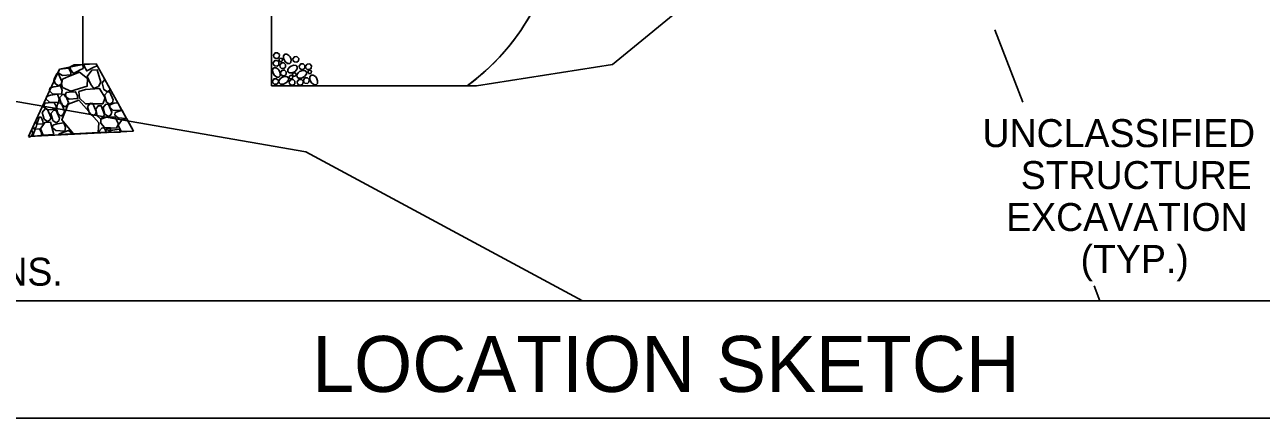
# Model space of a CAD drawing. Extents: x 471 to 2034, y -623 to 126.
# Drawn here: x 632.5 to 720.8, y -339.9 to -311.7 of the extents above; entities that cross this region are included whole.
import ezdxf

# ---------------------------------------------------------------- set-up
doc = ezdxf.new("R2010")
doc.units = 0
for name, color, linetype in [('Default', 7, 'Continuous'), ('Exist Hydro Stream or Body of Water', 7, 'Continuous'), ('Exist Vegetation Woods Line', 7, 'Continuous'), ('Miscellaneous Lines CELL', 7, 'Continuous'), ('Plan Sheet CELL', 7, 'Continuous'), ('Sup Concrete Girder Lines', 7, 'Continuous'), ('Text', 7, 'Continuous'), ('Title Text', 7, 'Continuous')]:
    doc.layers.add(name, color=color, linetype=linetype)

msp = doc.modelspace()

# ---------------------------------------------------------------- linework, layer by layer
at = {"layer": 'Default'}
for p, q in [((636.644, -299.662), (636.642, -314.576)), ((681.665, -308.67), (674.472, -314.579)), ((674.472, -314.579), (681.665, -308.67)), ((636.026, -314.603), (636.642, -314.575)), ((636.642, -314.575), (636.642, -314.575)), ((636.741, -314.572), (637.59, -314.535)), ((637.656, -314.654), (637.59, -314.535)), ((674.472, -314.579), (664.751, -316.1)), ((664.751, -316.1), (674.472, -314.579)), ((634.778, -315.233), (634.58, -315.676)), ((635.187, -315.643), (635.118, -315.981)), ((638.21, -315.651), (638.594, -316.343)), ((634.254, -316.406), (634.319, -316.262)), ((664.751, -316.1), (664.087, -316.1)), ((664.087, -316.1), (664.751, -316.1)), ((634.824, -317.421), (634.758, -317.744)), ((639.436, -317.867), (639.137, -317.319)), ((633.037, -319.141), (633.257, -318.64)), ((633.354, -318.85), (633.534, -318.346)), ((639.774, -318.47), (640.267, -319.35)), ((632.766, -319.739), (632.978, -319.263)), ((633.231, -319.208), (633.06, -319.695)), ((634.573, -319.596), (633.811, -319.63)), ((635.899, -319.539), (634.897, -319.582)), ((637.745, -319.456), (635.965, -319.533)), ((638.317, -319.431), (637.834, -319.452)), ((638.64, -319.266), (638.292, -319.281)), ((638.46, -319.449), (639.324, -319.412)), ((639.37, -319.385), (640.267, -319.346))]:
    msp.add_line(p, q, dxfattribs=at)
for points in [[(634.965, -314.907), (635.189, -314.885), (635.638, -314.852), (635.776, -315.147), (635.784, -315.334), (635.186, -315.373), (634.877, -315.173), (634.965, -314.907)], [(635.187, -315.643), (635.454, -315.503), (636.414, -315.135), (636.972, -315.587), (636.958, -316.125), (635.785, -316.489), (635.198, -316.227), (635.118, -315.981)], [(636.653, -314.875), (636.444, -314.959), (635.968, -315.217), (635.755, -314.939), (635.747, -314.752), (636.026, -314.603)], [(636.64, -314.576), (636.653, -314.875)], [(637.658, -314.681), (637.437, -314.778), (636.923, -315.038), (636.76, -314.745), (636.741, -314.572)], [(637.416, -316.305), (637.216, -316.014), (636.953, -315.437), (637.272, -314.998), (637.671, -314.968), (637.922, -315.858), (637.748, -316.166), (637.416, -316.305)], [(637.656, -314.654), (637.658, -314.681)], [(634.902, -316.118), (634.657, -315.953), (634.58, -315.676)], [(634.778, -315.233), (634.914, -315.254), (635.139, -315.807), (635.084, -315.997), (634.902, -316.118)], [(638.39, -316.54), (638.145, -316.375), (638.011, -315.893), (638.21, -315.651)], [(634.044, -316.882), (634.339, -316.781), (634.824, -316.71), (634.951, -317.042), (634.9, -317.307), (634.261, -317.273), (634.027, -317.07), (634.044, -316.882)], [(634.319, -316.262), (634.561, -316.179), (635.046, -316.108), (635.173, -316.44), (635.122, -316.705), (634.483, -316.671), (634.249, -316.468), (634.254, -316.406)], [(635.346, -317.609), (635.114, -317.444), (634.968, -316.963), (635.183, -316.728), (635.37, -316.72), (635.62, -317.297), (635.53, -317.526), (635.346, -317.609)], [(635.452, -316.591), (635.676, -316.569), (636.125, -316.537), (636.263, -316.831), (636.271, -317.018), (635.672, -317.057), (635.363, -316.858), (635.452, -316.591)], [(636.35, -316.527), (636.832, -316.381), (637.842, -316.312), (638.234, -316.97), (638.064, -317.391), (636.826, -317.395), (636.396, -317), (636.35, -316.527)], [(638.567, -317.433), (638.322, -317.269), (638.188, -316.786), (638.39, -316.54), (638.579, -316.569), (638.803, -317.123), (638.749, -317.313), (638.567, -317.433)], [(638.594, -316.343), (638.572, -316.419), (638.39, -316.54)], [(634.115, -318.655), (633.87, -318.491), (633.737, -318.009), (633.939, -317.762), (634.128, -317.791), (634.352, -318.345), (634.298, -318.535), (634.115, -318.655)], [(633.931, -317.35), (634.155, -317.328), (634.604, -317.296), (634.742, -317.59), (634.75, -317.777), (634.151, -317.816), (633.842, -317.617), (633.931, -317.35)], [(634.736, -318.744), (634.491, -318.579), (634.358, -318.097), (634.559, -317.851), (634.748, -317.88), (634.973, -318.433), (634.918, -318.623), (634.736, -318.744)], [(635.062, -318.272), (634.853, -318.056), (634.758, -317.744)], [(634.824, -317.421), (634.884, -317.342), (635.109, -317.332), (635.336, -317.948), (635.245, -318.152), (635.062, -318.272)], [(635.965, -319.534), (635.136, -318.532), (635.588, -317.411), (636.364, -317.127), (637.786, -318.754), (637.745, -319.456)], [(637.351, -318.248), (637.118, -318.083), (636.985, -317.6), (637.174, -317.354), (637.363, -317.384), (637.6, -317.936), (637.533, -318.127), (637.351, -318.248)], [(637.899, -318.474), (637.664, -318.259), (637.569, -317.788), (637.733, -317.543), (637.958, -317.533), (638.185, -318.161), (638.081, -318.353), (637.899, -318.474)], [(638.467, -318.311), (638.222, -318.147), (638.089, -317.665), (638.291, -317.418), (638.48, -317.448), (638.704, -318.001), (638.65, -318.191), (638.467, -318.311)], [(639.436, -317.867), (639.432, -317.884), (638.793, -317.849), (638.559, -317.647), (638.575, -317.458)], [(638.575, -317.458), (638.871, -317.358), (639.137, -317.319)], [(633.257, -318.637), (633.358, -318.885), (633.303, -319.075), (633.121, -319.195)], [(633.532, -318.349), (633.657, -318.34), (633.795, -318.634), (633.803, -318.822), (633.356, -318.851)], [(633.814, -319.627), (633.607, -319.173), (633.926, -318.734), (634.325, -318.704), (634.577, -319.594)], [(637.925, -318.498), (638.319, -318.355), (638.918, -318.317), (639.177, -318.819), (639.041, -319.137), (638.176, -319.1), (637.937, -318.785), (637.925, -318.498)], [(639.759, -318.436), (639.162, -318.403), (638.928, -318.201), (638.945, -318.012)], [(638.945, -318.012), (639.241, -317.912), (639.443, -317.882)], [(639.37, -319.385), (639.164, -318.931), (639.482, -318.492), (639.776, -318.47)], [(639.442, -317.882), (639.443, -317.882), (639.757, -318.435)], [(632.978, -319.262), (633.06, -319.466), (633.006, -319.656), (632.823, -319.776)], [(633.121, -319.195), (633.034, -319.137)], [(633.231, -319.208), (633.541, -319.186), (633.679, -319.48), (633.687, -319.668), (633.088, -319.706), (633.06, -319.696)], [(634.503, -318.922), (634.798, -318.822), (635.283, -318.751), (635.41, -319.083), (635.359, -319.348), (634.72, -319.313), (634.486, -319.111), (634.503, -318.922)], [(634.897, -319.58), (634.942, -319.541), (635.608, -319.299), (635.899, -319.536)], [(637.834, -319.452), (637.808, -319.357), (638.01, -319.111), (638.199, -319.14), (638.317, -319.431)], [(638.292, -319.281), (638.408, -319.139), (638.597, -319.168), (638.64, -319.266)], [(638.46, -319.449), (638.466, -319.382)], [(638.466, -319.382), (638.762, -319.282), (639.247, -319.21), (639.324, -319.412)], [(632.823, -319.776), (632.765, -319.737)]]:
    msp.add_lwpolyline(points, dxfattribs=at)
msp.add_arc((654.611, -303.102), 16.085, 306.09259, 354.38534, dxfattribs=at)
at = {"layer": 'Exist Hydro Stream or Body of Water'}
for points in [[(703.76, -317.276), (701.758, -312.107)], [(709.258, -331.475), (708.844, -330.406)]]:
    msp.add_lwpolyline(points, dxfattribs=at)
at = {"layer": 'Exist Vegetation Woods Line'}
msp.add_lwpolyline([(564.339, -320.555), (625.254, -316.095), (652.558, -320.834), (672.318, -331.475)], dxfattribs=at)
at = {"layer": 'Miscellaneous Lines CELL'}
for points in [[(650.229, -314.469), (650.341, -314.31), (650.52, -314.3), (650.645, -314.429), (650.627, -314.609), (650.516, -314.701), (650.34, -314.688), (650.256, -314.608), (650.229, -314.469)], [(650.261, -313.916), (650.373, -313.756), (650.552, -313.746), (650.676, -313.875), (650.658, -314.056), (650.548, -314.148), (650.371, -314.135), (650.288, -314.054), (650.261, -313.916)], [(650.646, -314.242), (650.713, -314.147), (650.82, -314.141), (650.895, -314.218), (650.884, -314.326), (650.818, -314.382), (650.712, -314.374), (650.662, -314.326), (650.646, -314.242)], [(651.437, -314.028), (651.52, -314.238), (651.503, -314.431), (651.416, -314.522), (651.26, -314.519), (651.083, -314.38), (650.975, -314.166), (650.972, -313.963), (651.053, -313.849), (651.214, -313.839), (651.358, -313.931), (651.442, -314.037)], [(651.638, -314.187), (651.75, -314.028), (651.929, -314.017), (652.054, -314.146), (652.036, -314.327), (651.925, -314.419), (651.748, -314.406), (651.665, -314.325), (651.638, -314.187)], [(650.657, -315.004), (650.741, -315.214), (650.724, -315.407), (650.637, -315.498), (650.481, -315.495), (650.303, -315.356), (650.196, -315.142), (650.192, -314.939), (650.273, -314.825), (650.434, -314.815), (650.578, -314.907), (650.663, -315.013)], [(650.703, -314.628), (650.815, -314.468), (650.994, -314.458), (651.118, -314.587), (651.1, -314.768), (650.99, -314.859), (650.813, -314.847), (650.73, -314.766), (650.703, -314.628)], [(650.753, -315.152), (650.865, -314.993), (651.044, -314.982), (651.168, -315.111), (651.15, -315.292), (651.039, -315.384), (650.863, -315.371), (650.78, -315.29), (650.753, -315.152)], [(651.462, -314.721), (651.671, -314.638), (651.864, -314.655), (651.955, -314.742), (651.952, -314.898), (651.813, -315.075), (651.599, -315.183), (651.397, -315.186), (651.283, -315.105), (651.272, -314.944), (651.364, -314.8), (651.47, -314.716)], [(651.612, -315.283), (651.68, -315.187), (651.787, -315.181), (651.862, -315.258), (651.851, -315.367), (651.785, -315.422), (651.679, -315.414), (651.629, -315.366), (651.613, -315.283)], [(652.112, -315.096), (652.322, -315.012), (652.514, -315.029), (652.606, -315.116), (652.603, -315.272), (652.464, -315.45), (652.249, -315.557), (652.047, -315.561), (651.933, -315.48), (651.922, -315.319), (652.015, -315.175), (652.12, -315.09)], [(652.087, -314.707), (652.199, -314.547), (652.378, -314.537), (652.502, -314.666), (652.484, -314.847), (652.373, -314.938), (652.197, -314.926), (652.114, -314.845), (652.087, -314.707)], [(652.548, -314.713), (652.66, -314.554), (652.839, -314.544), (652.963, -314.673), (652.945, -314.853), (652.834, -314.945), (652.658, -314.932), (652.575, -314.852), (652.548, -314.713)], [(652.711, -315.099), (652.778, -315.003), (652.885, -314.997), (652.96, -315.074), (652.949, -315.183), (652.883, -315.238), (652.777, -315.23), (652.727, -315.182), (652.711, -315.099)], [(650.185, -315.768), (650.297, -315.609), (650.476, -315.599), (650.6, -315.728), (650.582, -315.908), (650.472, -316), (650.295, -315.987), (650.212, -315.907), (650.185, -315.768)], [(650.831, -315.523), (651.041, -315.439), (651.233, -315.456), (651.325, -315.543), (651.322, -315.699), (651.183, -315.877), (650.968, -315.984), (650.766, -315.988), (650.652, -315.907), (650.641, -315.746), (650.734, -315.602), (650.839, -315.517)], [(651.374, -315.827), (651.486, -315.668), (651.665, -315.658), (651.789, -315.787), (651.771, -315.967), (651.661, -316.059), (651.484, -316.047), (651.401, -315.966), (651.374, -315.827)], [(651.381, -315.477), (651.449, -315.381), (651.556, -315.375), (651.63, -315.453), (651.62, -315.561), (651.553, -315.616), (651.447, -315.609), (651.398, -315.56), (651.381, -315.477)], [(651.952, -315.821), (652.064, -315.661), (652.243, -315.651), (652.367, -315.78), (652.349, -315.961), (652.239, -316.053), (652.062, -316.04), (651.979, -315.959), (651.952, -315.821)], [(652.386, -315.704), (652.499, -315.544), (652.677, -315.534), (652.802, -315.663), (652.784, -315.844), (652.673, -315.936), (652.497, -315.923), (652.414, -315.842), (652.387, -315.704)], [(653.321, -315.533), (653.404, -315.743), (653.388, -315.935), (653.301, -316.027), (653.145, -316.024), (652.967, -315.885), (652.86, -315.67), (652.856, -315.468), (652.937, -315.354), (653.098, -315.343), (653.242, -315.436), (653.327, -315.542)]]:
    msp.add_lwpolyline(points, dxfattribs=at)
at = {"layer": 'Plan Sheet CELL'}
msp.add_line((564.339, -331.475), (805.312, -331.475), dxfattribs=at)
msp.add_lwpolyline([(564.339, -339.883), (805.312, -339.883), (805.312, -229.69)], dxfattribs=at)
at = {"layer": 'Sup Concrete Girder Lines'}
for p, q in [((636.647, -275.822), (636.642, -314.576)), ((650.111, -304.992), (650.111, -316.1)), ((634.965, -314.907), (632.766, -319.739)), ((636.642, -314.575), (634.965, -314.907)), ((636.026, -314.603), (636.642, -314.575)), ((637.59, -314.535), (636.642, -314.576)), ((636.642, -314.575), (636.642, -314.575)), ((636.741, -314.572), (637.59, -314.535)), ((637.656, -314.654), (637.59, -314.535)), ((640.267, -319.346), (637.59, -314.535)), ((634.778, -315.233), (634.58, -315.676)), ((635.187, -315.643), (635.118, -315.981)), ((638.21, -315.651), (638.594, -316.343)), ((634.254, -316.406), (634.319, -316.262)), ((634.824, -317.421), (634.758, -317.744)), ((639.436, -317.867), (639.137, -317.319)), ((633.037, -319.141), (633.257, -318.64)), ((633.354, -318.85), (633.534, -318.346)), ((639.774, -318.47), (640.267, -319.35)), ((632.766, -319.739), (632.978, -319.263)), ((632.766, -319.739), (640.267, -319.346)), ((633.231, -319.208), (633.06, -319.695)), ((634.573, -319.596), (633.811, -319.63)), ((635.899, -319.539), (634.897, -319.582)), ((637.745, -319.456), (635.965, -319.533)), ((638.317, -319.431), (637.834, -319.452)), ((638.64, -319.266), (638.292, -319.281)), ((638.46, -319.449), (639.324, -319.412)), ((639.37, -319.385), (640.267, -319.346))]:
    msp.add_line(p, q, dxfattribs=at)
for points in [[(634.965, -314.907), (635.189, -314.885), (635.638, -314.852), (635.776, -315.147), (635.784, -315.334), (635.186, -315.373), (634.877, -315.173), (634.965, -314.907)], [(635.187, -315.643), (635.454, -315.503), (636.414, -315.135), (636.972, -315.587), (636.958, -316.125), (635.785, -316.489), (635.198, -316.227), (635.118, -315.981)], [(636.653, -314.875), (636.444, -314.959), (635.968, -315.217), (635.755, -314.939), (635.747, -314.752), (636.026, -314.603)], [(636.64, -314.576), (636.653, -314.875)], [(637.658, -314.681), (637.437, -314.778), (636.923, -315.038), (636.76, -314.745), (636.741, -314.572)], [(637.416, -316.305), (637.216, -316.014), (636.953, -315.437), (637.272, -314.998), (637.671, -314.968), (637.922, -315.858), (637.748, -316.166), (637.416, -316.305)], [(637.656, -314.654), (637.658, -314.681)], [(634.902, -316.118), (634.657, -315.953), (634.58, -315.676)], [(634.778, -315.233), (634.914, -315.254), (635.139, -315.807), (635.084, -315.997), (634.902, -316.118)], [(638.39, -316.54), (638.145, -316.375), (638.011, -315.893), (638.21, -315.651)], [(634.044, -316.882), (634.339, -316.781), (634.824, -316.71), (634.951, -317.042), (634.9, -317.307), (634.261, -317.273), (634.027, -317.07), (634.044, -316.882)], [(634.319, -316.262), (634.561, -316.179), (635.046, -316.108), (635.173, -316.44), (635.122, -316.705), (634.483, -316.671), (634.249, -316.468), (634.254, -316.406)], [(635.346, -317.609), (635.114, -317.444), (634.968, -316.963), (635.183, -316.728), (635.37, -316.72), (635.62, -317.297), (635.53, -317.526), (635.346, -317.609)], [(635.452, -316.591), (635.676, -316.569), (636.125, -316.537), (636.263, -316.831), (636.271, -317.018), (635.672, -317.057), (635.363, -316.858), (635.452, -316.591)], [(636.35, -316.527), (636.832, -316.381), (637.842, -316.312), (638.234, -316.97), (638.064, -317.391), (636.826, -317.395), (636.396, -317), (636.35, -316.527)], [(638.567, -317.433), (638.322, -317.269), (638.188, -316.786), (638.39, -316.54), (638.579, -316.569), (638.803, -317.123), (638.749, -317.313), (638.567, -317.433)], [(638.594, -316.343), (638.572, -316.419), (638.39, -316.54)], [(650.111, -316.1), (651.094, -316.1), (664.087, -316.1)], [(634.115, -318.655), (633.87, -318.491), (633.737, -318.009), (633.939, -317.762), (634.128, -317.791), (634.352, -318.345), (634.298, -318.535), (634.115, -318.655)], [(633.931, -317.35), (634.155, -317.328), (634.604, -317.296), (634.742, -317.59), (634.75, -317.777), (634.151, -317.816), (633.842, -317.617), (633.931, -317.35)], [(634.736, -318.744), (634.491, -318.579), (634.358, -318.097), (634.559, -317.851), (634.748, -317.88), (634.973, -318.433), (634.918, -318.623), (634.736, -318.744)], [(635.062, -318.272), (634.853, -318.056), (634.758, -317.744)], [(634.824, -317.421), (634.884, -317.342), (635.109, -317.332), (635.336, -317.948), (635.245, -318.152), (635.062, -318.272)], [(635.965, -319.534), (635.136, -318.532), (635.588, -317.411), (636.364, -317.127), (637.786, -318.754), (637.745, -319.456)], [(637.351, -318.248), (637.118, -318.083), (636.985, -317.6), (637.174, -317.354), (637.363, -317.384), (637.6, -317.936), (637.533, -318.127), (637.351, -318.248)], [(637.899, -318.474), (637.664, -318.259), (637.569, -317.788), (637.733, -317.543), (637.958, -317.533), (638.185, -318.161), (638.081, -318.353), (637.899, -318.474)], [(638.467, -318.311), (638.222, -318.147), (638.089, -317.665), (638.291, -317.418), (638.48, -317.448), (638.704, -318.001), (638.65, -318.191), (638.467, -318.311)], [(639.436, -317.867), (639.432, -317.884), (638.793, -317.849), (638.559, -317.647), (638.575, -317.458)], [(638.575, -317.458), (638.871, -317.358), (639.137, -317.319)], [(633.257, -318.637), (633.358, -318.885), (633.303, -319.075), (633.121, -319.195)], [(633.532, -318.349), (633.657, -318.34), (633.795, -318.634), (633.803, -318.822), (633.356, -318.851)], [(633.814, -319.627), (633.607, -319.173), (633.926, -318.734), (634.325, -318.704), (634.577, -319.594)], [(637.925, -318.498), (638.319, -318.355), (638.918, -318.317), (639.177, -318.819), (639.041, -319.137), (638.176, -319.1), (637.937, -318.785), (637.925, -318.498)], [(639.759, -318.436), (639.162, -318.403), (638.928, -318.201), (638.945, -318.012)], [(638.945, -318.012), (639.241, -317.912), (639.443, -317.882)], [(639.37, -319.385), (639.164, -318.931), (639.482, -318.492), (639.776, -318.47)], [(639.442, -317.882), (639.443, -317.882), (639.757, -318.435)], [(632.978, -319.262), (633.06, -319.466), (633.006, -319.656), (632.823, -319.776)], [(633.121, -319.195), (633.034, -319.137)], [(633.231, -319.208), (633.541, -319.186), (633.679, -319.48), (633.687, -319.668), (633.088, -319.706), (633.06, -319.696)], [(634.503, -318.922), (634.798, -318.822), (635.283, -318.751), (635.41, -319.083), (635.359, -319.348), (634.72, -319.313), (634.486, -319.111), (634.503, -318.922)], [(634.897, -319.58), (634.942, -319.541), (635.608, -319.299), (635.899, -319.536)], [(637.834, -319.452), (637.808, -319.357), (638.01, -319.111), (638.199, -319.14), (638.317, -319.431)], [(638.292, -319.281), (638.408, -319.139), (638.597, -319.168), (638.64, -319.266)], [(638.46, -319.449), (638.466, -319.382)], [(638.466, -319.382), (638.762, -319.282), (639.247, -319.21), (639.324, -319.412)], [(632.823, -319.776), (632.765, -319.737)]]:
    msp.add_lwpolyline(points, dxfattribs=at)
msp.add_arc((654.611, -303.102), 16.085, 306.09259, 3.95747, dxfattribs=at)

# ---------------------------------------------------------------- texts
at = {"layer": 'Text'}
for s, p in [('UNCLASSIFIED', (700.878, -320.491)), ('STRUCTURE', (703.61, -323.491)), ('EXCAVATION', (702.57, -326.491)), ('(TYP.)', (707.885, -329.491)), ('UTILITY PLANS & SPECIAL PROVISIONS.', (583.039, -330.401))]:
    msp.add_text(s, height=2, dxfattribs=at).set_placement(p)
at = {"layer": 'Title Text'}
msp.add_text('LOCATION SKETCH', height=4, dxfattribs=at).set_placement((653.027, -337.995))

doc.saveas('drawing.dxf')
